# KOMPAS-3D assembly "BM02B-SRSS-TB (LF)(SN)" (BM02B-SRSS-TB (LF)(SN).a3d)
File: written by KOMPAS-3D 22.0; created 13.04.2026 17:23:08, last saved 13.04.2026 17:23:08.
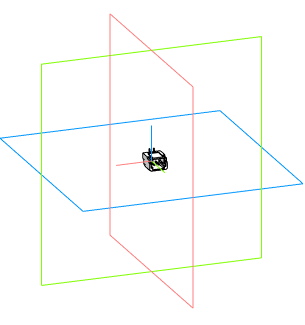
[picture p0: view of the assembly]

Document properties: Автор: Andrey; Полное имя файла: C:\Users\User1\Documents\BM02B-SRSS-TB (LF)(SN).a3d

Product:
- Component [detail]: BMxxB-SRSS-TB(LF)(SN)_02  | qty 1  | source file: BMxxB-SRSS-TB(LF)(SN)_02.m3d
- Part/product: BM02B-SRSS-TB (LF)(SN)

Referenced files in C:\Users\User1\Documents\: BMxxB-SRSS-TB(LF)(SN)_02.m3d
